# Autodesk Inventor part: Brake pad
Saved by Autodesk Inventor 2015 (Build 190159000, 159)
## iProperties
Created: 2015-04
Part Number: Brake pad
Material: Generic
Document SubType Name: Modeling
Designer: Gabriel Cabellos
Density: 1 g/cm^3
Appearance: Default
Author: Gabriel Cabellos
Sending System: SolidWorks 2011
Last Author: Pets
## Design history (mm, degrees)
node "Brake pad.ipt1"
node "Mirror1"
node "Base1"
